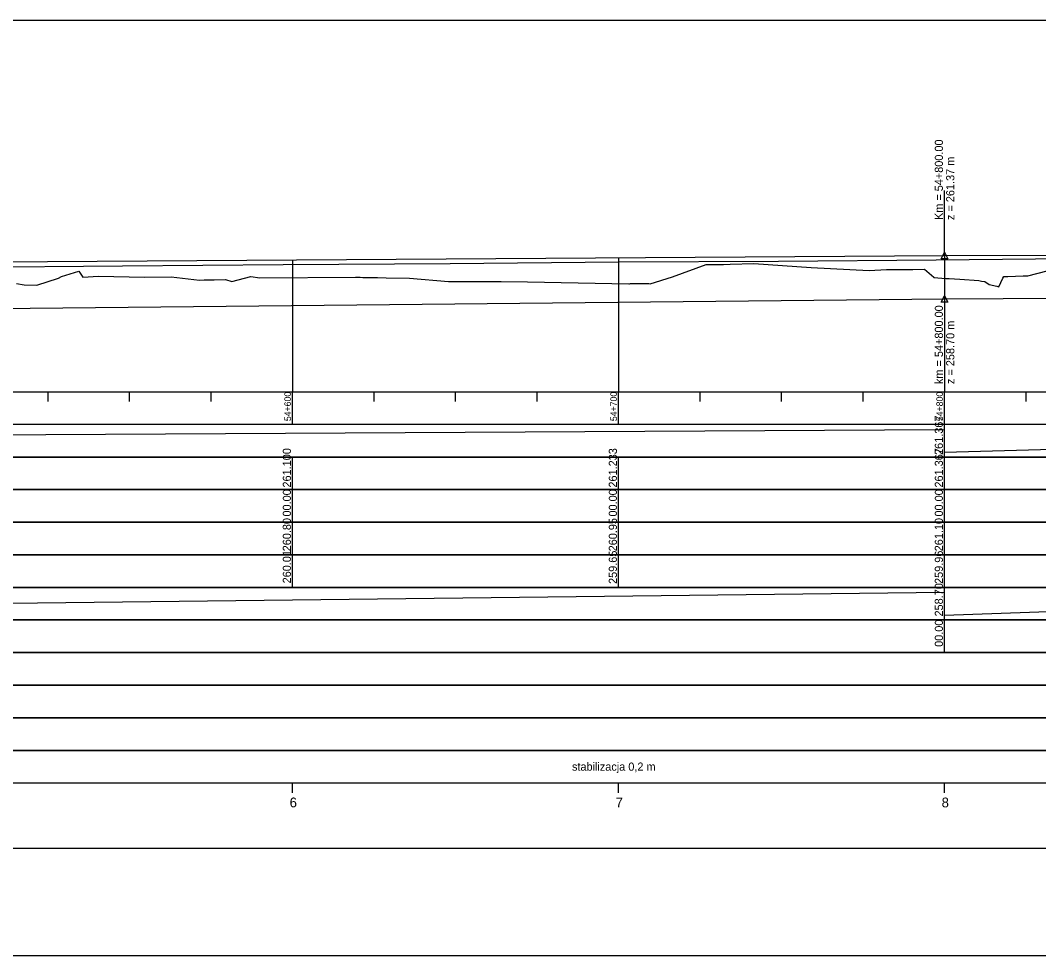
# Model space of a CAD drawing. Extents: x 6445630 to 6518227, y 5499240 to 5511716.
# Drawn here: x 6453747.7 to 6454060.1, y 5508418.3 to 5508705.3 of the extents above; entities that cross this region are included whole.
import ezdxf

# ---------------------------------------------------------------- set-up
doc = ezdxf.new("R2010")
doc.units = 0
for name, color, linetype in [('TOR_PROF-opisy pomocnicze', 7, 'Continuous'), ('TOR_PROF-rowy otwarte', 7, 'Continuous'), ('TOR_PROF-tabelka-geometria T1', 7, 'Continuous'), ('TOR_PROF-tabelka-kilometracja', 7, 'Continuous'), ('TOR_PROF-tabelka-odleglosci T1', 7, 'Continuous'), ('TOR_PROF-tabelka-pochylenia proj T1', 7, 'Continuous'), ('TOR_PROF-tabelka-rodzaj rowu T1', 7, 'Continuous'), ('TOR_PROF-tabelka-rowyT1', 7, 'Continuous'), ('TOR_PROF-tabelka-rurociagi T1', 7, 'Continuous'), ('TOR_PROF-tabelka-rzedne istn T1', 7, 'Continuous'), ('TOR_PROF-tabelka-rzedne proj T1', 7, 'Continuous'), ('TOR_PROF-tabelka-teren istniejacy T1', 7, 'Continuous'), ('TOR_PROF-tabelka-warstwa ochronna T1', 7, 'Continuous'), ('TOR_PROF-tor istniejacy T2', 7, 'Continuous'), ('TOR_PROF-tor projektowany', 7, 'Continuous'), ('TOR_PROF-uklad odniesienia', 7, 'Continuous'), ('TOR_PROF-warstwa ochronna', 7, 'Continuous'), ('TOR_RAMKI-dodatkowe3', 7, 'Continuous'), ('TOR_RAMKI-MASKA WYCIECIA', 7, 'Continuous')]:
    doc.layers.add(name, color=color, linetype=linetype)

msp = doc.modelspace()

# ---------------------------------------------------------------- linework, layer by layer
at = {"layer": 'TOR_PROF-opisy pomocnicze'}
for p, q in [((6454031.21, 5508633.12), (6454031.21, 5508653.12)), ((6454031.21, 5508633.12), (6454031.21, 5508653.12)), ((6454031.21, 5508619.79), (6454031.21, 5508592.79))]:
    msp.add_line(p, q, dxfattribs=at)
for points in [[(6454031.21, 5508634.12), (6454032.21, 5508632.12), (6454030.21, 5508632.12)], [(6454031.21, 5508634.12), (6454032.21, 5508632.12), (6454030.21, 5508632.12)], [(6454031.21, 5508620.79), (6454032.21, 5508618.79), (6454030.21, 5508618.79)]]:
    msp.add_lwpolyline(points, close=True, dxfattribs=at)
at = {"layer": 'TOR_PROF-rowy otwarte'}
for p, q in [((6453431.21, 5508613.79), (6454031.21, 5508619.79)), ((6454031.21, 5508619.79), (6454231.21, 5508621.29))]:
    msp.add_line(p, q, dxfattribs=at)
at = {"layer": 'TOR_PROF-tabelka-geometria T1'}
for points in [[(6452331.21, 5508451.29), (6453331.21, 5508451.29), (6453331.21, 5508448.62), (6453416.22, 5508448.62), (6453416.22, 5508451.29), (6453496.22, 5508451.29), (6453496.22, 5508453.96), (6453581.21, 5508453.96), (6453581.21, 5508451.29), (6457347.56, 5508451.29), (6457347.56, 5508448.62), (6457429.11, 5508448.62), (6457429.11, 5508451.29), (6457509.11, 5508451.29), (6457509.11, 5508453.96), (6457590.67, 5508453.96), (6457590.67, 5508451.29), (6459780.93, 5508451.29)], [(6452331.21, 5508451.29), (6462731.21, 5508451.29)]]:
    msp.add_lwpolyline(points, dxfattribs=at)
at = {"layer": 'TOR_PROF-tabelka-kilometracja'}
for points in [[(6453831.21, 5508468.29), (6453831.21, 5508471.29)], [(6453931.21, 5508468.29), (6453931.21, 5508471.29)], [(6454031.21, 5508468.29), (6454031.21, 5508471.29)]]:
    msp.add_lwpolyline(points, dxfattribs=at)
at = {"layer": 'TOR_PROF-tabelka-odleglosci T1'}
msp.add_lwpolyline([(6452331.21, 5508551.29), (6462731.21, 5508551.29), (6462731.21, 5508561.29), (6452331.21, 5508561.29)], close=True, dxfattribs=at)
for points in [[(6453831.21, 5508551.29), (6453831.21, 5508561.29)], [(6453931.21, 5508551.29), (6453931.21, 5508561.29)], [(6454031.21, 5508551.29), (6454031.21, 5508561.29)]]:
    msp.add_lwpolyline(points, dxfattribs=at)
at = {"layer": 'TOR_PROF-tabelka-pochylenia proj T1'}
msp.add_lwpolyline([(6452331.21, 5508571.29), (6462731.21, 5508571.29), (6462731.21, 5508581.29), (6452331.21, 5508581.29)], close=True, dxfattribs=at)
for points in [[(6452781.21, 5508572.79), (6454031.21, 5508579.79)], [(6454031.21, 5508571.29), (6454031.21, 5508581.29)], [(6454031.21, 5508572.79), (6454281.21, 5508579.79)]]:
    msp.add_lwpolyline(points, dxfattribs=at)
at = {"layer": 'TOR_PROF-tabelka-rodzaj rowu T1'}
for points in [[(6452331.21, 5508511.29), (6462731.21, 5508511.29), (6462731.21, 5508521.29), (6452331.21, 5508521.29)], [(6452331.21, 5508511.29), (6462731.21, 5508511.29), (6462731.21, 5508521.29), (6452331.21, 5508521.29)], [(6452331.21, 5508491.29), (6462731.21, 5508491.29), (6462731.21, 5508501.29), (6452331.21, 5508501.29)]]:
    msp.add_lwpolyline(points, close=True, dxfattribs=at)
msp.add_lwpolyline([(6454031.21, 5508511.29), (6454031.21, 5508521.29)], dxfattribs=at)
at = {"layer": 'TOR_PROF-tabelka-rowyT1'}
msp.add_lwpolyline([(6452331.21, 5508521.29), (6462731.21, 5508521.29), (6462731.21, 5508531.29), (6452331.21, 5508531.29)], close=True, dxfattribs=at)
msp.add_lwpolyline([(6452331.21, 5508521.29), (6462731.21, 5508521.29), (6462731.21, 5508531.29), (6452331.21, 5508531.29)], close=True, dxfattribs=at)
msp.add_lwpolyline([(6452331.21, 5508521.29), (6462731.21, 5508521.29), (6462731.21, 5508531.29), (6452331.21, 5508531.29)], close=True, dxfattribs=at)
for points in [[(6453431.21, 5508522.79), (6454031.21, 5508529.79)], [(6454031.21, 5508521.29), (6454031.21, 5508531.29)], [(6454031.21, 5508522.79), (6454231.21, 5508529.79)]]:
    msp.add_lwpolyline(points, dxfattribs=at)
at = {"layer": 'TOR_PROF-tabelka-rurociagi T1'}
msp.add_lwpolyline([(6452331.21, 5508501.29), (6462731.21, 5508501.29), (6462731.21, 5508511.29), (6452331.21, 5508511.29)], close=True, dxfattribs=at)
at = {"layer": 'TOR_PROF-tabelka-rzedne istn T1'}
msp.add_lwpolyline([(6452331.21, 5508541.29), (6462731.21, 5508541.29), (6462731.21, 5508551.29), (6452331.21, 5508551.29)], close=True, dxfattribs=at)
for points in [[(6453831.21, 5508541.29), (6453831.21, 5508551.29)], [(6453931.21, 5508541.29), (6453931.21, 5508551.29)], [(6454031.21, 5508541.29), (6454031.21, 5508551.29)], [(6453831.21, 5508531.29), (6453831.21, 5508541.29)], [(6453831.21, 5508531.29), (6453831.21, 5508541.29)], [(6453831.21, 5508531.29), (6453831.21, 5508541.29)], [(6453831.21, 5508531.29), (6453831.21, 5508541.29)], [(6453931.21, 5508531.29), (6453931.21, 5508541.29)], [(6453931.21, 5508531.29), (6453931.21, 5508541.29)], [(6453931.21, 5508531.29), (6453931.21, 5508541.29)], [(6453931.21, 5508531.29), (6453931.21, 5508541.29)], [(6454031.21, 5508531.29), (6454031.21, 5508541.29)], [(6454031.21, 5508531.29), (6454031.21, 5508541.29)], [(6454031.21, 5508531.29), (6454031.21, 5508541.29)], [(6454031.21, 5508531.29), (6454031.21, 5508541.29)]]:
    msp.add_lwpolyline(points, dxfattribs=at)
at = {"layer": 'TOR_PROF-tabelka-rzedne proj T1'}
msp.add_lwpolyline([(6452331.21, 5508561.29), (6462731.21, 5508561.29), (6462731.21, 5508571.29), (6452331.21, 5508571.29)], close=True, dxfattribs=at)
for points in [[(6453831.21, 5508561.29), (6453831.21, 5508571.29)], [(6453931.21, 5508561.29), (6453931.21, 5508571.29)], [(6454031.21, 5508561.29), (6454031.21, 5508571.29)]]:
    msp.add_lwpolyline(points, dxfattribs=at)
at = {"layer": 'TOR_PROF-tabelka-teren istniejacy T1'}
msp.add_lwpolyline([(6452331.21, 5508531.29), (6462731.21, 5508531.29), (6462731.21, 5508541.29), (6452331.21, 5508541.29)], close=True, dxfattribs=at)
msp.add_lwpolyline([(6452331.21, 5508531.29), (6462731.21, 5508531.29), (6462731.21, 5508541.29), (6452331.21, 5508541.29)], close=True, dxfattribs=at)
msp.add_lwpolyline([(6452331.21, 5508531.29), (6462731.21, 5508531.29), (6462731.21, 5508541.29), (6452331.21, 5508541.29)], close=True, dxfattribs=at)
msp.add_lwpolyline([(6452331.21, 5508531.29), (6462731.21, 5508531.29), (6462731.21, 5508541.29), (6452331.21, 5508541.29)], close=True, dxfattribs=at)
at = {"layer": 'TOR_PROF-tabelka-warstwa ochronna T1'}
msp.add_lwpolyline([(6452331.21, 5508481.29), (6462731.21, 5508481.29), (6462731.21, 5508491.29), (6452331.21, 5508491.29)], close=True, dxfattribs=at)
at = {"layer": 'TOR_PROF-tor istniejacy T2'}
msp.add_lwpolyline([(6454079.48, 5508632.24), (6454028.59, 5508631.74), (6453980.3, 5508631.29), (6453931.34, 5508631.04), (6453879.58, 5508630.59), (6453828.36, 5508630.29), (6453779.07, 5508629.84), (6453731.23, 5508629.44), (6453681.44, 5508629.09), (6453629.54, 5508628.54), (6453583.46, 5508628.39), (6453531.62, 5508627.99), (6453481.89, 5508627.69), (6453429.5, 5508627.34)], dxfattribs=at)
at = {"layer": 'TOR_PROF-tor projektowany'}
for p, q in [((6452781.21, 5508624.79), (6454031.21, 5508633.12)), ((6452781.21, 5508624.79), (6454031.21, 5508633.12)), ((6454031.21, 5508633.12), (6454281.21, 5508633.98)), ((6454031.21, 5508633.12), (6454281.21, 5508633.98))]:
    msp.add_line(p, q, dxfattribs=at)
for points in [[(6453831.21, 5508631.79), (6453831.21, 5508596.29), (6453831.21, 5508591.29), (6453831.21, 5508591.29)], [(6453831.21, 5508631.79), (6453831.21, 5508596.29), (6453831.21, 5508591.29), (6453831.21, 5508591.29)], [(6453931.21, 5508632.46), (6453931.21, 5508596.29), (6453931.21, 5508591.29), (6453931.21, 5508591.29)], [(6453931.21, 5508632.46), (6453931.21, 5508596.29), (6453931.21, 5508591.29), (6453931.21, 5508591.29)], [(6454031.21, 5508633.12), (6454031.21, 5508596.29), (6454031.21, 5508591.29), (6454031.21, 5508591.29)], [(6454031.21, 5508633.12), (6454031.21, 5508596.29), (6454031.21, 5508591.29), (6454031.21, 5508591.29)], [(6454031.21, 5508633.12), (6454031.21, 5508596.29), (6454031.21, 5508591.29), (6454031.21, 5508591.29)], [(6454031.21, 5508633.12), (6454031.21, 5508596.29), (6454031.21, 5508591.29), (6454031.21, 5508591.29)]]:
    msp.add_lwpolyline(points, dxfattribs=at)
at = {"layer": 'TOR_PROF-uklad odniesienia'}
for p, q in [((6452331.21, 5508591.29), (6462731.21, 5508591.29)), ((6452331.21, 5508591.29), (6462731.21, 5508591.29)), ((6453756.21, 5508588.29), (6453756.21, 5508591.29)), ((6453756.21, 5508588.29), (6453756.21, 5508591.29)), ((6453781.21, 5508588.29), (6453781.21, 5508591.29)), ((6453781.21, 5508588.29), (6453781.21, 5508591.29)), ((6453806.21, 5508588.29), (6453806.21, 5508591.29)), ((6453806.21, 5508588.29), (6453806.21, 5508591.29)), ((6453831.21, 5508581.29), (6453831.21, 5508591.29)), ((6453831.21, 5508581.29), (6453831.21, 5508591.29)), ((6453856.21, 5508588.29), (6453856.21, 5508591.29)), ((6453856.21, 5508588.29), (6453856.21, 5508591.29)), ((6453881.21, 5508588.29), (6453881.21, 5508591.29)), ((6453881.21, 5508588.29), (6453881.21, 5508591.29)), ((6453906.21, 5508588.29), (6453906.21, 5508591.29)), ((6453906.21, 5508588.29), (6453906.21, 5508591.29)), ((6453931.21, 5508581.29), (6453931.21, 5508591.29)), ((6453931.21, 5508581.29), (6453931.21, 5508591.29)), ((6453956.21, 5508588.29), (6453956.21, 5508591.29)), ((6453956.21, 5508588.29), (6453956.21, 5508591.29)), ((6453981.21, 5508588.29), (6453981.21, 5508591.29)), ((6453981.21, 5508588.29), (6453981.21, 5508591.29)), ((6454006.21, 5508588.29), (6454006.21, 5508591.29)), ((6454006.21, 5508588.29), (6454006.21, 5508591.29)), ((6454031.21, 5508581.29), (6454031.21, 5508591.29)), ((6454031.21, 5508581.29), (6454031.21, 5508591.29)), ((6454056.21, 5508588.29), (6454056.21, 5508591.29)), ((6454056.21, 5508588.29), (6454056.21, 5508591.29))]:
    msp.add_line(p, q, dxfattribs=at)
at = {"layer": 'TOR_PROF-warstwa ochronna'}
msp.add_lwpolyline([(6452331.21, 5508471.29), (6462731.21, 5508471.29), (6462731.21, 5508481.29), (6452331.21, 5508481.29)], close=True, dxfattribs=at)
at = {"layer": 'TOR_RAMKI-dodatkowe3'}
for p, q in [((6453947.78, 5508626.63), (6453958.1, 5508630.42)), ((6453958.1, 5508630.42), (6453963.39, 5508630.39)), ((6453963.39, 5508630.39), (6453965.42, 5508630.44)), ((6453965.42, 5508630.44), (6453972.68, 5508630.72)), ((6453972.68, 5508630.72), (6453990.29, 5508629.41)), ((6453990.29, 5508629.41), (6454008.08, 5508628.53)), ((6454008.08, 5508628.53), (6454013.36, 5508628.84)), ((6454013.36, 5508628.84), (6454021.49, 5508628.85)), ((6454021.49, 5508628.85), (6454025.05, 5508628.92)), ((6454025.05, 5508628.92), (6454027.89, 5508626.44)), ((6453752.75, 5508624), (6453759.43, 5508626.21)), ((6453759.43, 5508626.21), (6453760.38, 5508626.74)), ((6453760.38, 5508626.74), (6453765.64, 5508628.36)), ((6453765.64, 5508628.36), (6453766.85, 5508626.52)), ((6453766.85, 5508626.52), (6453771.65, 5508626.78)), ((6453771.65, 5508626.78), (6453785.76, 5508626.49)), ((6453785.76, 5508626.49), (6453793.93, 5508626.59)), ((6453793.93, 5508626.59), (6453802.64, 5508625.56)), ((6453802.64, 5508625.56), (6453804.06, 5508625.68)), ((6453804.06, 5508625.68), (6453807.2, 5508625.71)), ((6453807.2, 5508625.71), (6453810.69, 5508625.74)), ((6453810.69, 5508625.74), (6453812.61, 5508625.19)), ((6453812.61, 5508625.19), (6453818.44, 5508626.73)), ((6453818.44, 5508626.73), (6453821.22, 5508626.27)), ((6453821.22, 5508626.27), (6453850.53, 5508626.52)), ((6453850.53, 5508626.52), (6453851.92, 5508626.48)), ((6453851.92, 5508626.48), (6453852.72, 5508626.36)), ((6453852.72, 5508626.36), (6453857.31, 5508626.37)), ((6453857.31, 5508626.37), (6453859.95, 5508626.31)), ((6453859.95, 5508626.31), (6453867.08, 5508626.14)), ((6453867.08, 5508626.14), (6453879.01, 5508625.11)), ((6453940.91, 5508624.47), (6453947.78, 5508626.63)), ((6454027.89, 5508626.44), (6454027.93, 5508626.41)), ((6454027.93, 5508626.41), (6454031.63, 5508626.05)), ((6454031.63, 5508626.05), (6454032.58, 5508626.06)), ((6454032.58, 5508626.06), (6454035.91, 5508625.85)), ((6454035.91, 5508625.85), (6454041.72, 5508625.49)), ((6454041.72, 5508625.49), (6454042.53, 5508625.28)), ((6454047.83, 5508623.55), (6454049.12, 5508626.17)), ((6454049.12, 5508626.17), (6454049.35, 5508626.67)), ((6454049.35, 5508626.67), (6454050.63, 5508626.74)), ((6454050.63, 5508626.74), (6454055.31, 5508626.92)), ((6454055.31, 5508626.92), (6454056.74, 5508626.87)), ((6454056.74, 5508626.87), (6454062.64, 5508628.44)), ((6453746.53, 5508624.5), (6453748.9, 5508624.13)), ((6453748.9, 5508624.13), (6453752.75, 5508624)), ((6453879.01, 5508625.11), (6453895.16, 5508625.13)), ((6453895.16, 5508625.13), (6453903.27, 5508625.01)), ((6453903.27, 5508625.01), (6453934.39, 5508624.47)), ((6453934.39, 5508624.47), (6453934.52, 5508624.45)), ((6453934.52, 5508624.45), (6453934.83, 5508624.51)), ((6453934.83, 5508624.51), (6453935.47, 5508624.56)), ((6453935.47, 5508624.56), (6453940.48, 5508624.52)), ((6453940.48, 5508624.52), (6453940.91, 5508624.47)), ((6454042.53, 5508625.28), (6454043.57, 5508625.2)), ((6454043.57, 5508625.2), (6454044.87, 5508624.21)), ((6454044.87, 5508624.21), (6454047.24, 5508623.75)), ((6454047.24, 5508623.75), (6454047.83, 5508623.55))]:
    msp.add_line(p, q, dxfattribs=at)
at = {"layer": 'TOR_RAMKI-MASKA WYCIECIA'}
msp.add_lwpolyline([(6452266.8, 5508418.29), (6454296.8, 5508418.29), (6454296.8, 5508705.29), (6452266.8, 5508705.29)], close=True, dxfattribs=at)

# ---------------------------------------------------------------- texts
at = {"layer": 'TOR_PROF-opisy pomocnicze'}
for s, p in [('Km = 54+800.00', (6454030.71, 5508644.02)), ('Km = 54+800.00', (6454030.71, 5508644.02)), ('z = 261.37 m', (6454034.21, 5508644.02)), ('z = 261.37 m', (6454034.21, 5508644.02)), ('km = 54+800.00', (6454030.71, 5508593.69)), ('z = 258.70 m', (6454034.21, 5508593.69))]:
    msp.add_text(s, height=2.5, rotation=90, dxfattribs=at).set_placement(p)
at = {"layer": 'TOR_PROF-tabelka-kilometracja'}
for s, p in [('6', (6453830.32, 5508463.79)), ('7', (6453930.32, 5508463.79)), ('8', (6454030.32, 5508463.79))]:
    msp.add_text(s, height=3, dxfattribs=at).set_placement(p)
at = {"layer": 'TOR_PROF-tabelka-odleglosci T1'}
for p in [(6453830.71, 5508553.03), (6453930.71, 5508553.03), (6454030.71, 5508553.03)]:
    msp.add_text('00.00', height=2.5, rotation=90, dxfattribs=at).set_placement(p)
at = {"layer": 'TOR_PROF-tabelka-pochylenia proj T1'}
msp.add_text('261.367', height=2.5, rotation=90, dxfattribs=at).set_placement((6454030.71, 5508571.93))
at = {"layer": 'TOR_PROF-tabelka-rodzaj rowu T1'}
msp.add_text('00.00', height=2.5, rotation=90, dxfattribs=at).set_placement((6454030.71, 5508513.04))
at = {"layer": 'TOR_PROF-tabelka-rowyT1'}
msp.add_text('258.70', height=2.5, rotation=90, dxfattribs=at).set_placement((6454030.71, 5508522.36))
at = {"layer": 'TOR_PROF-tabelka-rzedne istn T1'}
for s, p in [('260.80', (6453830.71, 5508542.36)), ('260.95', (6453930.71, 5508542.35)), ('261.10', (6454030.71, 5508542.36)), ('260.01', (6453830.71, 5508532.52)), ('259.65', (6453930.71, 5508532.35)), ('259.96', (6454030.71, 5508532.35))]:
    msp.add_text(s, height=2.5, rotation=90, dxfattribs=at).set_placement(p)
at = {"layer": 'TOR_PROF-tabelka-rzedne proj T1'}
for s, p in [('261.100', (6453830.71, 5508561.93)), ('261.233', (6453930.71, 5508561.92)), ('261.367', (6454030.71, 5508561.93))]:
    msp.add_text(s, height=2.5, rotation=90, dxfattribs=at).set_placement(p)
at = {"layer": 'TOR_PROF-uklad odniesienia'}
for s, p in [('54+600', (6453830.71, 5508582.31)), ('54+600', (6453830.71, 5508582.31)), ('54+700', (6453930.71, 5508582.31)), ('54+700', (6453930.71, 5508582.31)), ('54+800', (6454030.71, 5508582.31)), ('54+800', (6454030.71, 5508582.31))]:
    msp.add_text(s, height=2, rotation=90, dxfattribs=at).set_placement(p)
at = {"layer": 'TOR_PROF-warstwa ochronna'}
msp.add_text('stabilizacja 0,2 m', height=2.5, rotation=360, dxfattribs=at).set_placement((6453916.92, 5508475.04))

doc.saveas('drawing.dxf')
